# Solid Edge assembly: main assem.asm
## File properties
Author: Robert a Rhodes jr
Template: Normal.asm
Last saved by: Robert a Rhodes jr
Revision: 10
Application: Solid Edge
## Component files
master rod.par
piston.par
piston pin.par
arti subassm.asm
piston pin plug.par
piston ring.par
master rod bearing.par
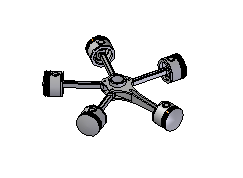
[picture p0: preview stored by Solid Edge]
